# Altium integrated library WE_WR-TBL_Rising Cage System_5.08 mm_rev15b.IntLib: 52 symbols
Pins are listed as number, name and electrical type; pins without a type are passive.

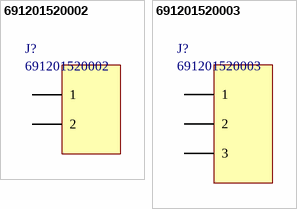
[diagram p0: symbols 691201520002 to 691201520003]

## 691201520002
designator J?
45° Cable Entry with Rising Cage Clamp, Serie 2015 - 5.08 mm; Manufacturer: Wurth Elektronik; ComponentLink1 Description: Manufacturer; ComponentLink2 Description: Datasheet; NoPins: 2
footprint 691201520002 (Serie 2015 - 5.08 mm _ 2 pins)
pins: 1, 2

## 691201520003
designator J?
45° Cable Entry with Rising Cage Clamp, Serie 2015 - 5.08 mm; Manufacturer: Wurth Elektronik; ComponentLink1 Description: Manufacturer; ComponentLink2 Description: Datasheet; NoPins: 3
footprint 691201520003 (Serie 2015 - 5.08 mm _ 3 pins)
pins: 1, 2, 3


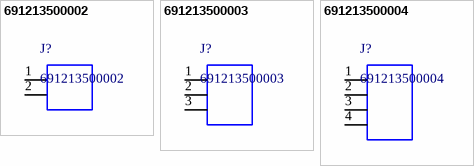
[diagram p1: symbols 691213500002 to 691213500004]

## 691213500002
designator J?
WR-TBL Vertical Cable Entry With Rising Cage Clamp,Serie 2135 - 5.08 mm; Manufacturer: Wurth Elektronik; ComponentLink1 Description: Manufacturer; ComponentLink2 Description: Datasheet
footprint 691213500002 (Serie 2135 - 5.08 mm _ 2 pins)
pins: 1, 2

## 691213500003
designator J?
WR-TBL Vertical Cable Entry With Rising Cage Clamp,Serie 2135 - 5.08 mm; Manufacturer: Wurth Elektronik; ComponentLink1 Description: Manufacturer; ComponentLink2 Description: Datasheet
footprint 691213500003 (Serie 2135 - 5.08 mm_ 3 pins)
pins: 1, 2, 3

## 691213500004
designator J?
WR-TBL Vertical Cable Entry With Rising Cage Clamp,Serie 2135 - 5.08 mm; Manufacturer: Wurth Elektronik; ComponentLink1 Description: Manufacturer; ComponentLink2 Description: Datasheet
footprint 691213500004 (Serie 2135 - 5.08 mm_ 4 pins)
pins: 1, 2, 3, 4


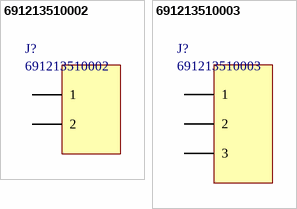
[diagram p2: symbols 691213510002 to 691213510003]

## 691213510002
designator J?
Horizontal Cable Entry with Rising Cage Clamp, Serie 2135 - 5.08 mm; Manufacturer: Wurth Elektronik; ComponentLink1 Description: Manufacturer; ComponentLink2 Description: Datasheet; NoPins: 2
footprint 691213510002 (Serie 2135 - 5.08 mm _ 2 pins)
pins: 1, 2

## 691213510003
designator J?
Horizontal Cable Entry with Rising Cage Clamp, Serie 2135 - 5.08 mm; Manufacturer: Wurth Elektronik; ComponentLink1 Description: Manufacturer; ComponentLink2 Description: Datasheet; NoPins: 3
footprint 691213510003 (Serie 2135 - 5.08 mm _ 3 pins)
pins: 1, 2, 3


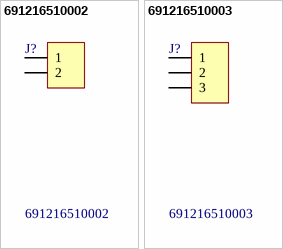
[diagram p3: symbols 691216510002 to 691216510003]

## 691216510002
designator J?
WR-TBL Horizontal Entry Modular with Rising Cage Clamp,Serie 2165 - 5.08 mm; Manufacturer: Würth Elektronik eiSos GmbH; ComponentLink1 Description: Manufacturer; ComponentLink2 Description: Datasheet; NoPins: 2
footprint 691216510002 (5,08mm - Modular - Horizontal wire entry - Rising cage clamp - 02p)
pins: 1, 2

## 691216510003
designator J?
WR-TBL Horizontal Entry Modular with Rising Cage Clamp,Serie 2165 - 5.08 mm; Manufacturer: Würth Elektronik eiSos GmbH; ComponentLink1 Description: Manufacturer; ComponentLink2 Description: Datasheet; NoPins: 3
footprint 691216510003 (5,08mm - Modular - Horizontal wire entry - Rising cage clamp - 03p)
pins: 1, 2, 3


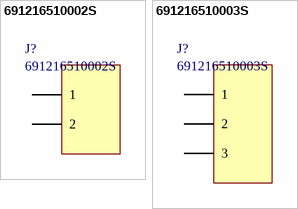
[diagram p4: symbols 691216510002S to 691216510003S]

## 691216510002S
designator J?
Horizontal Cable Entry with Rising Cage Clamp, Serie 2165S - 5.08 mm; Manufacturer: Wurth Elektronik; ComponentLink1 Description: Manufacturer; ComponentLink2 Description: Datasheet; NoPins: 2
footprint 691216510002S (Serie 2165S - 5.08 mm _ 2 pins)
pins: 1, 2

## 691216510003S
designator J?
Horizontal Cable Entry with Rising Cage Clamp, Serie 2165S - 5.08 mm; Manufacturer: Wurth Elektronik; ComponentLink1 Description: Manufacturer; ComponentLink2 Description: Datasheet; NoPins: 3
footprint 691216510003S (Serie 2165S - 5.08 mm _ 3 pins)
pins: 1, 2, 3


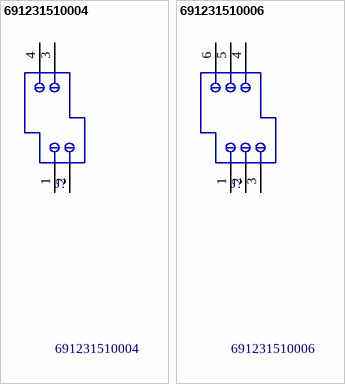
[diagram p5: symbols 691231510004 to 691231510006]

## 691231510004
designator J?
WR-TBL Double Level Horizontal Entry Modular with Rising Cage,Serie 2315 - 5.08 mm; Manufacturer: Würth Elektronik eiSos GmbH; ComponentLink1 Description: Manufacturer; ComponentLink2 Description: Datasheet; NoPins: 4
footprint 691231510004 (5,08mm - modular - 2 rows - Right - horizontal entry with rising cage clamp - 04p - h=19,1mm)
pins: 1, 2, 3, 4

## 691231510006
designator J?
WR-TBL Double Level Horizontal Entry Modular with Rising Cage,Serie 2315 - 5.08 mm; Manufacturer: Würth Elektronik eiSos GmbH; ComponentLink1 Description: Manufacturer; ComponentLink2 Description: Datasheet; NoPins: 6
footprint 691231510006 (5,08mm - modular - 2 rows - Right - horizontal entry with rising cage clamp - 06p - h=19,1mm)
pins: 1, 2, 3, 4, 5, 6


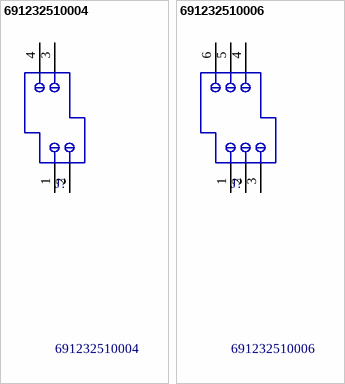
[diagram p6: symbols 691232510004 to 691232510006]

## 691232510004
designator J?
WR-TBL Double Level Horizontal Entry Modular with Rising Clamp,Serie 2325 - 5.08 mm; Manufacturer: Würth Elektronik eiSos GmbH; ComponentLink1 Description: Manufacturer; ComponentLink2 Description: Datasheet; NoPins: 4
footprint 691232510004 (5,08mm - modular - 2 rows - Right - horizontal entry with rising cage clamp - 04p - h=25,3mm)
pins: 1, 2, 3, 4

## 691232510006
designator J?
WR-TBL Double Level Horizontal Entry Modular with Rising Clamp,Serie 2325 - 5.08 mm; Manufacturer: Würth Elektronik eiSos GmbH; ComponentLink1 Description: Manufacturer; ComponentLink2 Description: Datasheet; NoPins: 6
footprint 691232510006 (5,08mm - modular - 2 rows - Right - horizontal entry with rising cage clamp - 06p - h=25,3mm)
pins: 1, 2, 3, 4, 5, 6


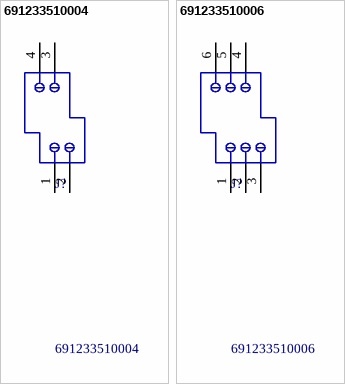
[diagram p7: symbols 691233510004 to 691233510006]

## 691233510004
designator J?
WR-TBL Double Level Horizontal Entry Modular with Rising Clamp,Serie 2335 - 5.08 mm; Manufacturer: Würth Elektronik eiSos GmbH; ComponentLink1 Description: Manufacturer; ComponentLink2 Description: Datasheet; NoPins: 4
footprint 691233510004 (5,08mm - modular - 2 rows - Right - horizontal entry with rising cage clamp - 04p - h=31,5mm)
pins: 1, 2, 3, 4

## 691233510006
designator J?
WR-TBL Double Level Horizontal Entry Modular with Rising Clamp,Serie 2335 - 5.08 mm; Manufacturer: Würth Elektronik eiSos GmbH; ComponentLink1 Description: Manufacturer; ComponentLink2 Description: Datasheet; NoPins: 6
footprint 691233510006 (5,08mm - modular - 2 rows - Right - horizontal entry with rising cage clamp - 06p - h=31,5mm)
pins: 1, 2, 3, 4, 5, 6


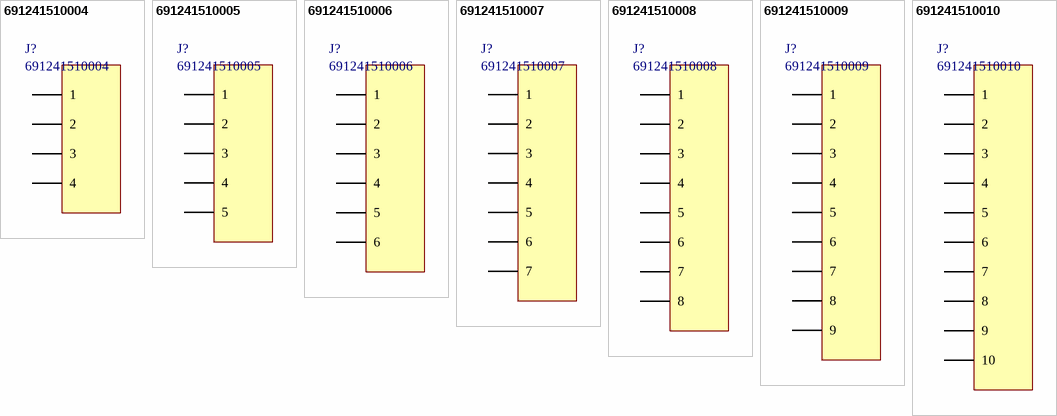
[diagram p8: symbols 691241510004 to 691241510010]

## 691241510004
designator J?
Horizontal Cable Entry with Rising Cage Clamp, Serie 2415 - 5.08 mm; Manufacturer: Wurth Elektronik; ComponentLink1 Description: Manufacturer; ComponentLink2 Description: Datasheet; NoPins: 4
footprint 691241510004 (Serie 2415 - 5.08 mm _ 4 pins)
pins: 1, 2, 3, 4

## 691241510005
designator J?
Horizontal Cable Entry with Rising Cage Clamp, Serie 2415 - 5.08 mm; Manufacturer: Wurth Elektronik; ComponentLink1 Description: Manufacturer; ComponentLink2 Description: Datasheet; NoPins: 5
footprint 691241510005 (Serie 2415 - 5.08 mm _ 5 pins)
pins: 1, 2, 3, 4, 5

## 691241510006
designator J?
Horizontal Cable Entry with Rising Cage Clamp, Serie 2415 - 5.08 mm; Manufacturer: Wurth Elektronik; ComponentLink1 Description: Manufacturer; ComponentLink2 Description: Datasheet; NoPins: 6
footprint 691241510006 (Serie 2415 - 5.08 mm _ 6 pins)
pins: 1, 2, 3, 4, 5, 6

## 691241510007
designator J?
Horizontal Cable Entry with Rising Cage Clamp, Serie 2415 - 5.08 mm; Manufacturer: Wurth Elektronik; ComponentLink1 Description: Manufacturer; ComponentLink2 Description: Datasheet; NoPins: 7
footprint 691241510007 (Serie 2415 - 5.08 mm _ 7 pins)
pins: 1, 2, 3, 4, 5, 6, 7

## 691241510008
designator J?
Horizontal Cable Entry with Rising Cage Clamp, Serie 2415 - 5.08 mm; Manufacturer: Wurth Elektronik; ComponentLink1 Description: Manufacturer; ComponentLink2 Description: Datasheet; NoPins: 8
footprint 691241510008 (Serie 2415 - 5.08 mm _ 8 pins)
pins: 1, 2, 3, 4, 5, 6, 7, 8

## 691241510009
designator J?
Horizontal Cable Entry with Rising Cage Clamp, Serie 2415 - 5.08 mm; Manufacturer: Wurth Elektronik; ComponentLink1 Description: Manufacturer; ComponentLink2 Description: Datasheet; NoPins: 9
footprint 691241510009 (Serie 2415 - 5.08 mm _ 9 pins)
pins: 1, 2, 3, 4, 5, 6, 7, 8, 9

## 691241510010
designator J?
Horizontal Cable Entry with Rising Cage Clamp, Serie 2415 - 5.08 mm; Manufacturer: Wurth Elektronik; ComponentLink1 Description: Manufacturer; ComponentLink2 Description: Datasheet; NoPins: 10
footprint 691241510010 (Serie 2415 - 5.08 mm _ 10 pins)
pins: 1, 2, 3, 4, 5, 6, 7, 8, 9, 10


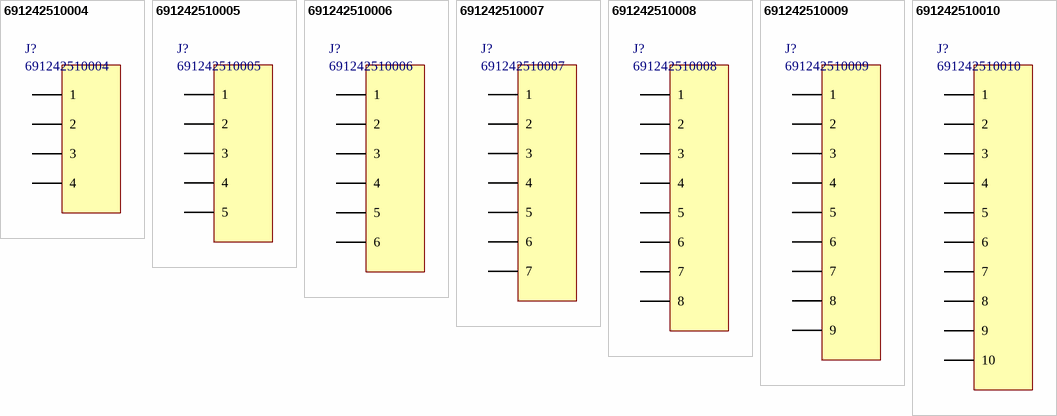
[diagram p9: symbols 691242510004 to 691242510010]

## 691242510004
designator J?
Horizontal Cable Entry with Rising Cage Clamp, Serie 2425 - 5.08 mm; Manufacturer: Wurth Elektronik; ComponentLink1 Description: Manufacturer; ComponentLink2 Description: Datasheet; NoPins: 4
footprint 691242510004 (Serie 2425 - 5.08 mm _ 4 pins)
pins: 1, 2, 3, 4

## 691242510005
designator J?
Horizontal Cable Entry with Rising Cage Clamp, Serie 2425 - 5.08 mm; Manufacturer: Wurth Elektronik; ComponentLink1 Description: Manufacturer; ComponentLink2 Description: Datasheet; NoPins: 5
footprint 691242510005 (Serie 2425 - 5.08 mm _ 5 pins)
pins: 1, 2, 3, 4, 5

## 691242510006
designator J?
Horizontal Cable Entry with Rising Cage Clamp, Serie 2425 - 5.08 mm; Manufacturer: Wurth Elektronik; ComponentLink1 Description: Manufacturer; ComponentLink2 Description: Datasheet; NoPins: 6
footprint 691242510006 (Serie 2425 - 5.08 mm _ 6 pins)
pins: 1, 2, 3, 4, 5, 6

## 691242510007
designator J?
Horizontal Cable Entry with Rising Cage Clamp, Serie 2425 - 5.08 mm; Manufacturer: Wurth Elektronik; ComponentLink1 Description: Manufacturer; ComponentLink2 Description: Datasheet; NoPins: 7
footprint 691242510007 (Serie 2425 - 5.08 mm _ 7 pins)
pins: 1, 2, 3, 4, 5, 6, 7

## 691242510008
designator J?
Horizontal Cable Entry with Rising Cage Clamp, Serie 2425 - 5.08 mm; Manufacturer: Wurth Elektronik; ComponentLink1 Description: Manufacturer; ComponentLink2 Description: Datasheet; NoPins: 8
footprint 691242510008 (Serie 2425 - 5.08 mm _ 8 pins)
pins: 1, 2, 3, 4, 5, 6, 7, 8

## 691242510009
designator J?
Horizontal Cable Entry with Rising Cage Clamp, Serie 2425 - 5.08 mm; Manufacturer: Wurth Elektronik; ComponentLink1 Description: Manufacturer; ComponentLink2 Description: Datasheet; NoPins: 9
footprint 691242510009 (Serie 2425 - 5.08 mm _ 9 pins)
pins: 1, 2, 3, 4, 5, 6, 7, 8, 9

## 691242510010
designator J?
Horizontal Cable Entry with Rising Cage Clamp, Serie 2425 - 5.08 mm; Manufacturer: Wurth Elektronik; ComponentLink1 Description: Manufacturer; ComponentLink2 Description: Datasheet; NoPins: 10
footprint 691242510010 (Serie 2425 - 5.08 mm _ 10 pins)
pins: 1, 2, 3, 4, 5, 6, 7, 8, 9, 10


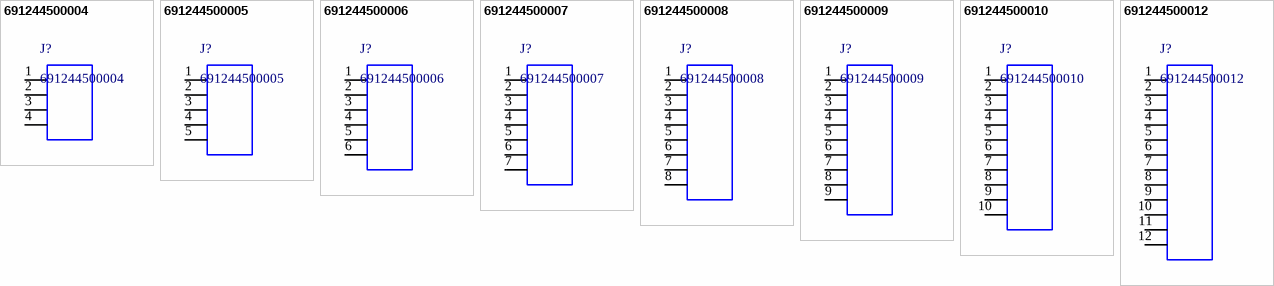
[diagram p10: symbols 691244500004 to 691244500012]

## 691244500004
designator J?
WR-TBL Vertical Cable Entry With Rising Cage Clamp,Serie 2445 - 5.08 mm; Manufacturer: Wurth Elektronik; ComponentLink1 Description: Manufacturer; ComponentLink2 Description: Datasheet
footprint 691244500004 (Serie 2445 - 5.08 mm _ 4 pins)
pins: 1, 2, 3, 4

## 691244500005
designator J?
WR-TBL Vertical Cable Entry With Rising Cage Clamp,Serie 2445 - 5.08 mm; Manufacturer: Wurth Elektronik; ComponentLink1 Description: Manufacturer; ComponentLink2 Description: Datasheet
footprint 691244500005 (Serie 2445 - 5.08 mm _ 5 pins)
pins: 1, 2, 3, 4, 5

## 691244500006
designator J?
WR-TBL Vertical Cable Entry With Rising Cage Clamp,Serie 2445 - 5.08 mm; Manufacturer: Wurth Elektronik; ComponentLink1 Description: Manufacturer; ComponentLink2 Description: Datasheet
footprint 691244500006 (Serie 2445 - 5.08 mm _ 6 pins)
pins: 1, 2, 3, 4, 5, 6

## 691244500007
designator J?
WR-TBL Vertical Cable Entry With Rising Cage Clamp,Serie 2445 - 5.08 mm; Manufacturer: Wurth Elektronik; ComponentLink1 Description: Manufacturer; ComponentLink2 Description: Datasheet
footprint 691244500007 (Serie 2445 - 5.08 mm _ 7 pins)
pins: 1, 2, 3, 4, 5, 6, 7

## 691244500008
designator J?
WR-TBL Vertical Cable Entry With Rising Cage Clamp,Serie 2445 - 5.08 mm; Manufacturer: Wurth Elektronik; ComponentLink1 Description: Manufacturer; ComponentLink2 Description: Datasheet
footprint 691244500008 (Serie 2445 - 5.08 mm _ 8 pins)
pins: 1, 2, 3, 4, 5, 6, 7, 8

## 691244500009
designator J?
WR-TBL Vertical Cable Entry With Rising Cage Clamp,Serie 2445 - 5.08 mm; Manufacturer: Wurth Elektronik; ComponentLink1 Description: Manufacturer; ComponentLink2 Description: Datasheet
footprint 691244500009 (Serie 2445 - 5.08 mm _ 9 pins)
pins: 1, 2, 3, 4, 5, 6, 7, 8, 9

## 691244500010
designator J?
WR-TBL Vertical Cable Entry With Rising Cage Clamp,Serie 2445 - 5.08 mm; Manufacturer: Wurth Elektronik; ComponentLink1 Description: Manufacturer; ComponentLink2 Description: Datasheet
footprint 691244500010 (Serie 2445 - 5.08 mm _ 10 pins)
pins: 1, 2, 3, 4, 5, 6, 7, 8, 9, 10

## 691244500012
designator J?
WR-TBL Vertical Cable Entry With Rising Cage Clamp,Serie 2445 - 5.08 mm; Manufacturer: Wurth Elektronik; ComponentLink1 Description: Manufacturer; ComponentLink2 Description: Datasheet
footprint 691244500012 (Serie 2445 - 5.08 mm _ 12 pins)
pins: 1, 2, 3, 4, 5, 6, 7, 8, 9, 10, 11, 12


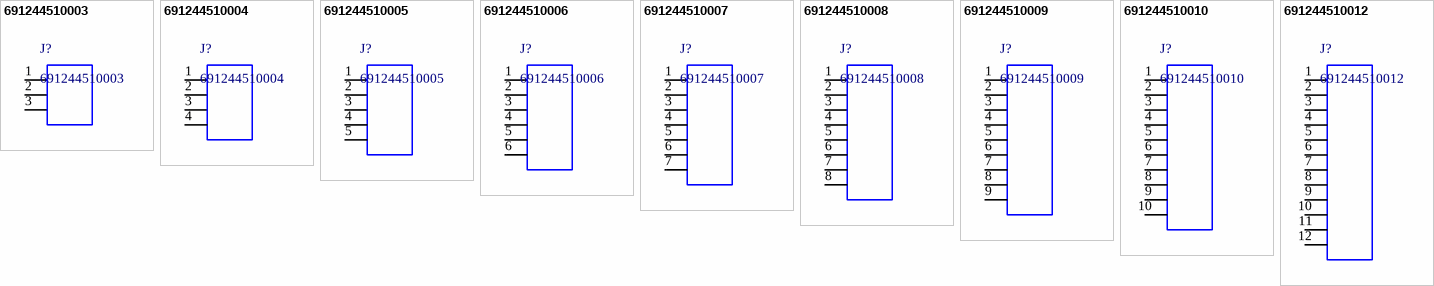
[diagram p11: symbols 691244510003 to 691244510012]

## 691244510003
designator J?
WR-TBL Horizontal Cable Entry With Rising Cage Clamp,Serie 2445 - 5.08 mm; Manufacturer: Wurth Elektronik; ComponentLink1 Description: Manufacturer; ComponentLink2 Description: Datasheet
footprint 691244510003 (Serie 2445 - 5.08 mm _ 3 pins)
pins: 1, 2, 3

## 691244510004
designator J?
WR-TBL Horizontal Cable Entry With Rising Cage Clamp,Serie 2445 - 5.08 mm; Manufacturer: Wurth Elektronik; ComponentLink1 Description: Manufacturer; ComponentLink2 Description: Datasheet
footprint 691244510004 (Serie 2445 - 5.08 mm _ 4 pins)
pins: 1, 2, 3, 4

## 691244510005
designator J?
WR-TBL Horizontal Cable Entry With Rising Cage Clamp,Serie 2445 - 5.08 mm; Manufacturer: Wurth Elektronik; ComponentLink1 Description: Manufacturer; ComponentLink2 Description: Datasheet
footprint 691244510005 (Serie 2445 - 5.08 mm _ 5 pins)
pins: 1, 2, 3, 4, 5

## 691244510006
designator J?
WR-TBL Horizontal Cable Entry With Rising Cage Clamp,Serie 2445 - 5.08 mm; Manufacturer: Wurth Elektronik; ComponentLink1 Description: Manufacturer; ComponentLink2 Description: Datasheet
footprint 691244510006 (Serie 2445 - 5.08 mm _ 6 pins)
pins: 1, 2, 3, 4, 5, 6

## 691244510007
designator J?
WR-TBL Horizontal Cable Entry With Rising Cage Clamp,Serie 2445 - 5.08 mm; Manufacturer: Wurth Elektronik; ComponentLink1 Description: Manufacturer; ComponentLink2 Description: Datasheet
footprint 691244510007 (Serie 2445 - 5.08 mm _ 7 pins)
pins: 1, 2, 3, 4, 5, 6, 7

## 691244510008
designator J?
WR-TBL Horizontal Cable Entry With Rising Cage Clamp,Serie 2445 - 5.08 mm; Manufacturer: Wurth Elektronik; ComponentLink1 Description: Manufacturer; ComponentLink2 Description: Datasheet
footprint 691244510008 (Serie 2445 - 5.08 mm _ 8 pins)
pins: 1, 2, 3, 4, 5, 6, 7, 8

## 691244510009
designator J?
WR-TBL Horizontal Cable Entry With Rising Cage Clamp,Serie 2445 - 5.08 mm; Manufacturer: Wurth Elektronik; ComponentLink1 Description: Manufacturer; ComponentLink2 Description: Datasheet
footprint 691244510009 (Serie 2445 - 5.08 mm _ 9 pins)
pins: 1, 2, 3, 4, 5, 6, 7, 8, 9

## 691244510010
designator J?
WR-TBL Horizontal Cable Entry With Rising Cage Clamp,Serie 2445 - 5.08 mm; Manufacturer: Wurth Elektronik; ComponentLink1 Description: Manufacturer; ComponentLink2 Description: Datasheet
footprint 691244510010 (Serie 2445 - 5.08 mm _ 10 pins)
pins: 1, 2, 3, 4, 5, 6, 7, 8, 9, 10

## 691244510012
designator J?
WR-TBL Horizontal Cable Entry With Rising Cage Clamp,Serie 2445 - 5.08 mm; Manufacturer: Wurth Elektronik; ComponentLink1 Description: Manufacturer; ComponentLink2 Description: Datasheet
footprint 691244510012 (Serie 2445 - 5.08 mm _ 12 pins)
pins: 1, 2, 3, 4, 5, 6, 7, 8, 9, 10, 11, 12


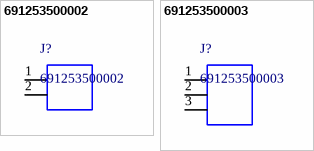
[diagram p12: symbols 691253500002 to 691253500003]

## 691253500002
designator J?
WR-TBL Vertical Cable Entry With Rising Cage Clamp,Serie 2535 - 5.08 mm; Manufacturer: Wurth Elektronik; ComponentLink1 Description: Manufacturer; ComponentLink2 Description: Datasheet
footprint 691253500002 (Serie 2535 - 5.08 mm _ 2 pins)
pins: 1, 2

## 691253500003
designator J?
WR-TBL Vertical Cable Entry With Rising Cage Clamp,Serie 2535 - 5.08 mm; Manufacturer: Wurth Elektronik; ComponentLink1 Description: Manufacturer; ComponentLink2 Description: Datasheet
footprint 691253500003 (Serie 2535 - 5.08 mm _ 3 pins)
pins: 1, 2, 3


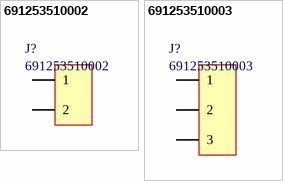
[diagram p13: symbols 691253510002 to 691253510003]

## 691253510002
designator J?
Horizontal Cable Entry with Rising Cage Clamp, Serie 2535 - 5.08mm; Manufacturer: Wurth Elektronik; ComponentLink1 Description: Manufacturer; ComponentLink2 Description: Datasheet; NoPins: 2
footprint 691253510002 (Serie 2535 - 5.08 mm _ 2 pins)
pins: 1, 2

## 691253510003
designator J?
Horizontal Cable Entry with Rising Cage Clamp, Serie 2535 - 5.08mm; Manufacturer: Wurth Elektronik; ComponentLink1 Description: Manufacturer; ComponentLink2 Description: Datasheet; NoPins: 3
footprint 691253510003 (Serie 2535 - 5.08 mm _ 3 pins)
pins: 1, 2, 3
